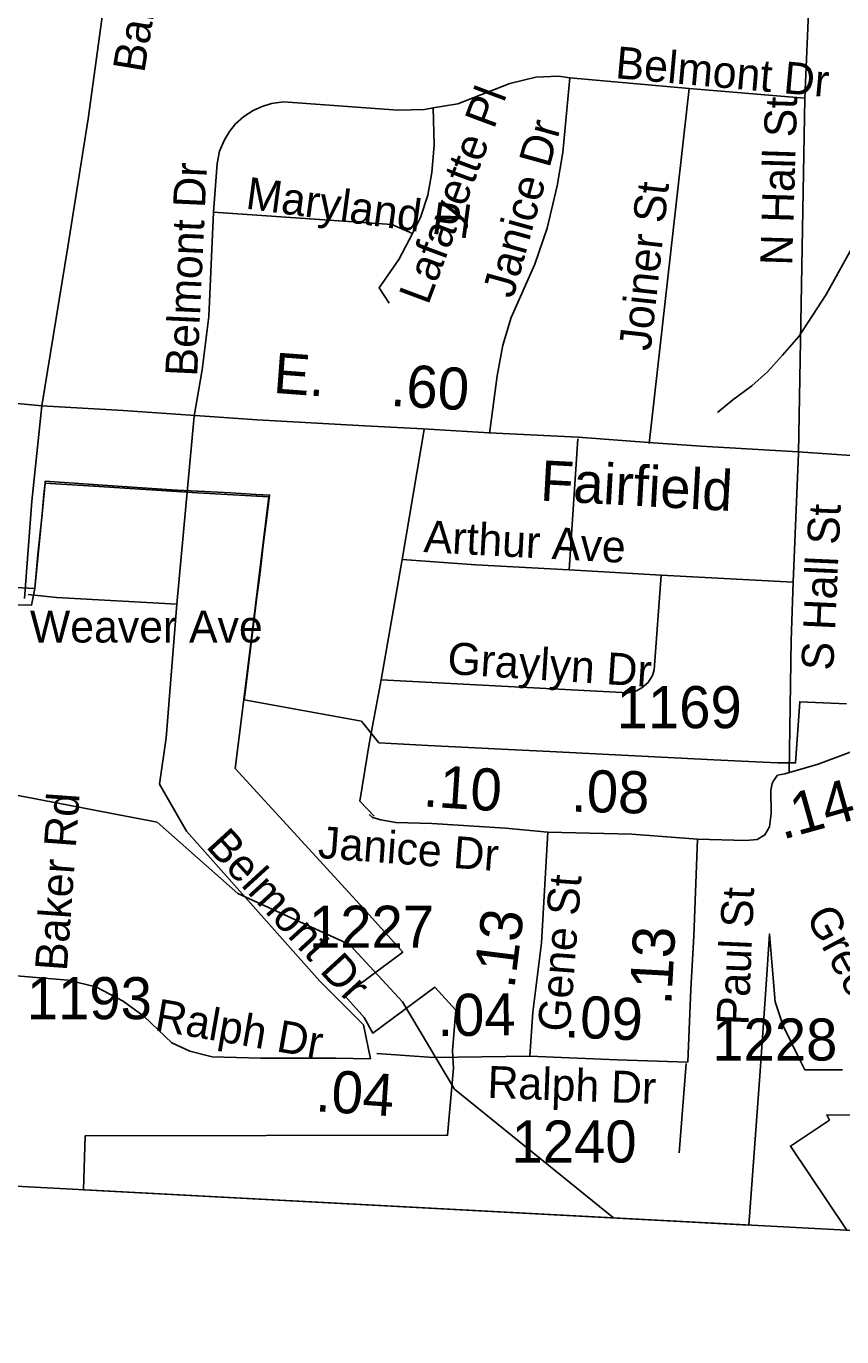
# Model space of a CAD drawing. Extents: x 1662474 to 1856135, y 779280 to 917889.
# Drawn here: x 1711933 to 1714357, y 789954 to 793848 of the extents above; entities that cross this region are included whole.
import ezdxf

# ---------------------------------------------------------------- set-up
doc = ezdxf.new("R2010")
doc.units = 0
for name, color, linetype in [('Exist Boundary Political City Limit New', 7, 'Continuous'), ('Exist Boundary Political CountyLine', 7, 'Continuous'), ('Exist Hydrographic Misc Water Feature', 7, 'Continuous'), ('Exist Road Non-System Type 51', 7, 'Continuous'), ('Exist Road Non-System Type 51 Label', 7, 'Continuous'), ('Exist Road Primary NC Attributed', 7, 'Continuous'), ('Exist Road Primary NC Label', 7, 'Continuous'), ('Exist Road Primary NC Mileage Hundredths English Label', 7, 'Continuous'), ('Exist Road Secondary Mileage Hundredths English Label', 7, 'Continuous'), ('Exist Road Secondary Mileage Tenths English Label', 7, 'Continuous'), ('Exist Road Secondary Type 51 Attributed', 7, 'Continuous'), ('Exist Road Secondary Type 51 Label', 7, 'Continuous'), ('Exist Road Secondary Type 51 Number Label', 7, 'Continuous'), ('Map Preparation Boundary City Limit Buffer Line', 7, 'Continuous')]:
    doc.layers.add(name, color=color, linetype=linetype)

msp = doc.modelspace()

# ---------------------------------------------------------------- linework, layer by layer
at = {"layer": 'Exist Boundary Political City Limit New'}
for points in [[(1711989.4, 792490.1), (1711958.4, 792176.9), (1711949.4, 792127.5), (1711899.6, 792128.6), (1711739.2, 792144.4), (1711711.2, 792147.1), (1711696, 792037.6), (1711687.4, 791927.7), (1711222.6, 791971.8), (1711122.2, 791981.2), (1711099.5, 791754.2), (1711348.9, 791737.2), (1711348.4, 791735.3), (1711873.5, 791696.8), (1711809, 790781.6), (1711807.5, 790781.6)], [(1711958.4, 792176.9), (1711968.9, 792288.8), (1711969.6, 792297.1), (1711980.4, 792396.9), (1711985.1, 792446.6), (1711988.8, 792483.4), (1711989.4, 792490.1)], [(1711989.4, 792490.1), (1711990, 792496.5), (1712189.4, 792482.6), (1712233.1, 792479.6), (1712293, 792475.4), (1712365.8, 792470.3), (1712382.8, 792469.1), (1712442.6, 792466.4), (1712444, 792466.3), (1712540.8, 792461.1), (1712616.2, 792456.9), (1712656.2, 792454.8), (1712650.1, 792405.1), (1712642.5, 792343.5), (1712637.8, 792305.5), (1712631.1, 792251.9), (1712630.1, 792244.1), (1712629, 792234.6), (1712625, 792202.1), (1712618.8, 792152.4), (1712611.6, 792094.7), (1712605.5, 792045.3), (1712598.8, 791990.9), (1712584.6, 791876.6), (1712580.9, 791846.5), (1712929.4, 791783.3), (1712981.2, 791718.6), (1713127.8, 791710.8), (1713247.6, 791704.7), (1713345.4, 791699.7), (1713488.8, 791692.4), (1713605.6, 791686.5), (1713722.8, 791680.6), (1713976.5, 791667.8), (1714122.5, 791660.9), (1714167.1, 791658.8), (1714219.4, 791658.8), (1714231.8, 791840.6), (1714370.4, 791834.7)], [(1714358.4, 790746.9), (1714246.8, 790747.2), (1714225.5, 790790.6), (1714182.6, 790877.9), (1714165.5, 790928.5), (1714159.1, 790948.9), (1714150, 791055.3), (1714141.8, 791150.6), (1714131.6, 791000.4), (1714113.4, 790729.3), (1714080, 790285.9), (1712103.2, 790390.4), (1712108.1, 790550.5), (1713185.5, 790552.5), (1713202.9, 790752.4), (1713200.4, 790803.4), (1713209.4, 790923.9), (1713147.2, 790992.4), (1712963, 790856.2), (1712937.8, 790902.4), (1712922.4, 790919.8), (1712878.6, 790968.1), (1713052.8, 791096.7), (1712925.4, 791237.1), (1712554.5, 791642.4), (1712591.6, 791942.1), (1712654.5, 792449.4), (1712442.1, 792461), (1712134.6, 792480.9), (1711989.4, 792490.1)], [(1711902.6, 792180.4), (1711958.4, 792176.9)], [(1714372.1, 790270.5), (1714204.1, 790520.2), (1714319.8, 790597.5), (1714312.2, 790612.9), (1714424, 790611.8)]]:
    msp.add_lwpolyline(points, dxfattribs=at)
at = {"layer": 'Exist Boundary Political CountyLine'}
msp.add_lwpolyline([(1690037.5, 791664.5), (1701364.2, 790957.5), (1714716, 790252.3), (1740499.2, 788706.5), (1750629.1, 788065.3), (1759370.2, 787540.1), (1762189.4, 787333), (1768414.3, 786933.6), (1776472.8, 786425.7), (1794607.1, 785397.2), (1814974.6, 784258.7), (1839558.3, 782880.6)], dxfattribs=at)
at = {"layer": 'Exist Hydrographic Misc Water Feature'}
for points in [[(1715151.2, 794379.7), (1715141, 794365.8), (1715053.8, 794246.6), (1714960.6, 794117.5), (1714899.6, 794006), (1714856.7, 793918.3), (1714791.8, 793826.9), (1714746.9, 793737.3), (1714661.5, 793598.1), (1714625, 793542.4), (1714590.6, 793492.7), (1714550.2, 793443.1), (1714507.5, 793385.5), (1714424.3, 793258.2), (1714375.4, 793168.7), (1714310.3, 793051.3), (1714229.2, 792925.9), (1714180.6, 792870.4), (1714136.1, 792820.9), (1714089.6, 792779.3), (1714033.2, 792737.8), (1713986.9, 792700.2)], [(1713678.2, 790307.1), (1713206.2, 790690), (1713051.1, 790949.2), (1712894.2, 791119.8), (1712562.1, 791271), (1712322.1, 791482.7), (1710999.1, 791736.1)]]:
    msp.add_lwpolyline(points, dxfattribs=at)
at = {"layer": 'Exist Road Non-System Type 51'}
for p, q in [((1714247.1, 793634.4), (1714260.6, 793950.8)), ((1713548.5, 793694.9), (1713903.4, 793663.1)), ((1713783.9, 792608), (1713903.4, 793663.1)), ((1713903.4, 793663.1), (1714247.1, 793634.4)), ((1714227.8, 792579.6), (1714247.1, 793634.4)), ((1712380.4, 792130.9), (1712432.5, 792689.6)), ((1713115.5, 792649.4), (1713050.4, 792263.6)), ((1713572.1, 792621.9), (1713546.6, 792232.4)), ((1714227.8, 792579.6), (1714212, 792195.9)), ((1713050.4, 792263.6), (1712987.9, 791905.6)), ((1713546.6, 792232.4), (1713820.4, 792217.2)), ((1713820.4, 792217.2), (1714212, 792195.9)), ((1713893.9, 790765.8), (1713873.1, 790500.2))]:
    msp.add_line(p, q, dxfattribs=at)
for points in [[(1713142.8, 793605.4), (1713215.8, 793617.7), (1713370.1, 793677.5), (1713447.2, 793696.4), (1713515.1, 793699.6), (1713548.5, 793694.9)], [(1713548.5, 793694.9), (1713527.5, 793473), (1713511, 793373.4), (1713481.1, 793247.6), (1713444.1, 793141.2), (1713374.5, 792982), (1713349.9, 792900.4), (1713332.8, 792809.2), (1713309.4, 792638.2)], [(1712490.2, 793295.6), (1712500.2, 793439.7), (1712508.1, 793476.4), (1712522, 793510.4), (1712537.2, 793535.5), (1712555.6, 793557.9), (1712580, 793579.9), (1712607.4, 793597.7), (1712633.9, 793609.8), (1712661.9, 793618.2), (1712698.1, 793622.9), (1713037.8, 793598.5), (1713116.5, 793600.4), (1713142.8, 793605.4)], [(1713142.8, 793605.4), (1713145.4, 793494.9), (1713138.9, 793412.9), (1713126.5, 793346.2), (1713104.6, 793279.4), (1713081.4, 793231.6)], [(1712490.2, 793295.6), (1712476.4, 792985.7), (1712456.1, 792826.6), (1712432.5, 792689.6)], [(1712490.2, 793295.6), (1713019.9, 793258.9), (1713081.4, 793231.6)], [(1713081.4, 793231.6), (1713040.1, 793155.2), (1712981.9, 793070.4), (1713011.5, 793025.5)], [(1713050.4, 792263.6), (1713268.8, 792247.9), (1713546.6, 792232.4)], [(1712987.9, 791905.6), (1713722.9, 791867), (1713746.6, 791873.4), (1713762.9, 791881.8), (1713781.1, 791897.8), (1713793.9, 791918.8), (1713799.4, 791935.9), (1713820.4, 792217.2)], [(1714212, 792195.9), (1714206.5, 792022.7), (1714199.9, 791631.4)], [(1711938.9, 792159.4), (1712022.9, 792150), (1712380.4, 792130.9)], [(1712955.9, 790779.2), (1712935.6, 790880.7), (1712805.5, 791010.9), (1712409.1, 791456.5), (1712329.6, 791595.4), (1712349.6, 791733.7), (1712380.4, 792130.9)], [(1712987.9, 791905.6), (1712952.2, 791715.6), (1712924.6, 791545.8), (1712966.7, 791500.6)], [(1711856.9, 791030.5), (1712057.9, 791013.4), (1712140.1, 790994.1), (1712221, 790951.4), (1712283.4, 790905.7), (1712366.1, 790827.2), (1712419.9, 790802.2), (1712485.9, 790785.9), (1712630.4, 790781.8), (1712853.5, 790781.8), (1712955.9, 790779.2)]]:
    msp.add_lwpolyline(points, dxfattribs=at)
at = {"layer": 'Exist Road Primary NC Attributed'}
for points in [[(1709810.5, 792964.2), (1710227.5, 793013.7), (1710304.9, 793022.3), (1710368.3, 793029.3), (1710434.8, 793035.6), (1710492.6, 793031.6), (1710554.4, 793024.6), (1710629.9, 793001.9), (1710677.6, 792982.4), (1710737.8, 792948), (1710833.3, 792892.9), (1710920.8, 792844.7), (1710990, 792811.9), (1711028.4, 792797.8), (1711083.9, 792783.7), (1711138.6, 792773.6), (1711202, 792766.5), (1711325.5, 792760.3), (1711389.7, 792756.4), (1711580.4, 792746.3), (1711834.2, 792733.6), (1711980.1, 792720.4)], [(1711980.1, 792720.4), (1712221, 792706.3), (1712434.9, 792691.5), (1712619.8, 792678.2), (1712939.3, 792660.2), (1713112.9, 792651.6), (1713308.8, 792639.8), (1713573.2, 792626.5), (1713782.4, 792610.9), (1713938.8, 792599.9), (1714227, 792583.5), (1714556.6, 792560.8), (1714732.6, 792548.3), (1714909.3, 792539.7), (1715082.8, 792532.6), (1715161.7, 792534.6)]]:
    msp.add_lwpolyline(points, dxfattribs=at)
at = {"layer": 'Exist Road Secondary Type 51 Attributed'}
for points in [[(1711980.1, 792720.4), (1712057.3, 793192.1), (1712117.7, 793573.1), (1712168.9, 793949.6), (1712234, 794372.5), (1712271.2, 794651.3), (1712289.2, 794759), (1712329.2, 794912.6), (1712473.9, 795357.1), (1712559.9, 795520.4), (1712593.7, 795605.5), (1712625.8, 795705.1), (1712648.3, 795803), (1712674.7, 795925.5), (1712699.3, 796156.8), (1712781.9, 796663.3), (1712836.2, 796867.3), (1712887.2, 796972.5), (1712944.6, 797071.4), (1713225.3, 797396.5), (1713368.9, 797536.8), (1713589, 797689.8), (1713974.4, 797851.7), (1714335.6, 798017.4)], [(1711927.7, 792148), (1711949.8, 792437), (1711980.1, 792720.4)], [(1714478.4, 791728.6), (1714436.3, 791713.1), (1714368.6, 791686), (1714286, 791654.9), (1714187, 791627), (1714166.1, 791622.4), (1714153.9, 791606.1), (1714149.8, 791598), (1714145.7, 791577.7), (1714147.1, 791508.7), (1714141.7, 791469.4), (1714128.1, 791445), (1714105.1, 791431.5), (1714071.2, 791428.8), (1713927.6, 791432.8)], [(1713482.8, 791453.6), (1713357.1, 791464.6), (1713138.3, 791478.8), (1713031.6, 791482.3), (1712987.2, 791489.5), (1712962.3, 791496.6), (1712952.8, 791505.3)], [(1713482.8, 791453.6), (1713464, 791124.1), (1713438.2, 790918.7), (1713429.4, 790787.8)], [(1713927.6, 791432.8), (1713733.1, 791446.9), (1713482.8, 791453.6)], [(1713927.6, 791432.8), (1713917.2, 791144.4), (1713908.6, 790986.3), (1713898.9, 790769.3)], [(1713429.4, 790787.8), (1713143.9, 790784.1), (1712975.4, 790795.5)], [(1713898.9, 790769.3), (1713688.8, 790776.3), (1713429.4, 790787.8)]]:
    msp.add_lwpolyline(points, dxfattribs=at)
at = {"layer": 'Map Preparation Boundary City Limit Buffer Line'}
for points in [[(1711989.4, 792490.1), (1711958.4, 792176.9), (1711949.4, 792127.5), (1711899.6, 792128.6), (1711739.2, 792144.4), (1711711.2, 792147.1), (1711696, 792037.6), (1711687.4, 791927.7), (1711222.6, 791971.8), (1711122.2, 791981.2), (1711099.5, 791754.2), (1711348.9, 791737.2), (1711348.4, 791735.3), (1711873.5, 791696.8), (1711809, 790781.6), (1711807.5, 790781.6)], [(1711958.4, 792176.9), (1711968.9, 792288.8), (1711969.6, 792297.1), (1711980.4, 792396.9), (1711985.1, 792446.6), (1711988.8, 792483.4), (1711989.4, 792490.1)], [(1711989.4, 792490.1), (1711990, 792496.5), (1712189.4, 792482.6), (1712233.1, 792479.6), (1712293, 792475.4), (1712365.8, 792470.3), (1712382.8, 792469.1), (1712442.6, 792466.4), (1712444, 792466.3), (1712540.8, 792461.1), (1712616.2, 792456.9), (1712656.2, 792454.8), (1712650.1, 792405.1), (1712642.5, 792343.5), (1712637.8, 792305.5), (1712631.1, 792251.9), (1712630.1, 792244.1), (1712629, 792234.6), (1712625, 792202.1), (1712618.8, 792152.4), (1712611.6, 792094.7), (1712605.5, 792045.3), (1712598.8, 791990.9), (1712584.6, 791876.6), (1712580.9, 791846.5), (1712929.4, 791783.3), (1712981.2, 791718.6), (1713127.8, 791710.8), (1713247.6, 791704.7), (1713345.4, 791699.7), (1713488.8, 791692.4), (1713605.6, 791686.5), (1713722.8, 791680.6), (1713976.5, 791667.8), (1714122.5, 791660.9), (1714167.1, 791658.8), (1714219.4, 791658.8), (1714231.8, 791840.6), (1714370.4, 791834.7)], [(1714358.4, 790746.9), (1714246.8, 790747.2), (1714225.5, 790790.6), (1714182.6, 790877.9), (1714165.5, 790928.5), (1714159.1, 790948.9), (1714150, 791055.3), (1714141.8, 791150.6), (1714131.6, 791000.4), (1714113.4, 790729.3), (1714080, 790285.9), (1712103.2, 790390.4), (1712108.1, 790550.5), (1713185.5, 790552.5), (1713202.9, 790752.4), (1713200.4, 790803.4), (1713209.4, 790923.9), (1713147.2, 790992.4), (1712963, 790856.2), (1712937.8, 790902.4), (1712922.4, 790919.8), (1712878.6, 790968.1), (1713052.8, 791096.7), (1712925.4, 791237.1), (1712554.5, 791642.4), (1712591.6, 791942.1), (1712654.5, 792449.4), (1712442.1, 792461), (1712134.6, 792480.9), (1711989.4, 792490.1)], [(1711902.6, 792180.4), (1711958.4, 792176.9)], [(1714372.1, 790270.5), (1714204.1, 790520.2), (1714319.8, 790597.5), (1714312.2, 790612.9), (1714424, 790611.8)]]:
    msp.add_lwpolyline(points, dxfattribs=at)

# ---------------------------------------------------------------- texts
at = {"layer": 'Exist Road Non-System Type 51 Label'}
for s, rotation, p in [('Belmont Dr', 354.8701, (1713681.7, 793693.9)), ('Lafayette Pl', 69.4915, (1713127.4, 793017)), ('N Hall St', 88.2649, (1714209, 793136)), ('Janice Dr', 74.4822, (1713379.9, 793036.4)), ('Belmont Dr', 87.3553, (1712441.2, 792805.9)), ('Maryland Pl', 352.3577, (1712582.7, 793306.3)), ('Joiner St', 83.7296, (1713788.5, 792881.3)), ('S Hall St', 87.3873, (1714331.1, 791932.2)), ('Arthur Ave', 356.8988, (1713112.8, 792285.6)), ('Graylyn Dr', 356.3146, (1713182.9, 791923.5)), ('Belmont Dr', 312.4177, (1712464.4, 791409.7)), ('Ralph Dr', 350.1354, (1712311.8, 790865.3))]:
    msp.add_text(s, height=95, rotation=rotation, dxfattribs=at).set_placement(p)
msp.add_text('Weaver Ave', height=95, dxfattribs=at).set_placement((1711944.2, 792016.7))
at = {"layer": 'Exist Road Primary NC Label'}
for s, rotation, p in [('E.', 355.7598, (1712665.5, 792758.8)), ('Fairfield', 356.8434, (1713458.9, 792438.7))]:
    msp.add_text(s, height=120, rotation=rotation, dxfattribs=at).set_placement(p)
at = {"layer": 'Exist Road Primary NC Mileage Hundredths English Label'}
msp.add_text('.60', height=125, rotation=356.5732, dxfattribs=at).set_placement((1713013.6, 792720.1))
at = {"layer": 'Exist Road Secondary Mileage Hundredths English Label'}
for s, rotation, p in [('.08', 358.4487, (1713551.2, 791514.3)), ('.14', 15.7181, (1714180.3, 791430.4)), ('.13', 82.8377, (1713383.5, 790985.3)), ('.04', 0.7479, (1713155.9, 790846.8)), ('.04', 356.1322, (1712790.8, 790624.2))]:
    msp.add_text(s, height=125, rotation=rotation, dxfattribs=at).set_placement(p)
at = {"layer": 'Exist Road Secondary Mileage Tenths English Label'}
for s, rotation, p in [('.10', 356.2816, (1713110.6, 791529.9)), ('.13', 86.8869, (1713849.9, 790937.6)), ('.09', 357.4458, (1713530.5, 790844.1))]:
    msp.add_text(s, height=125, rotation=rotation, dxfattribs=at).set_placement(p)
at = {"layer": 'Exist Road Secondary Type 51 Label'}
for s, rotation, p in [('Baker Rd', 80.6609, (1712283.9, 793707.3)), ('Baker Rd', 85.8448, (1712053.9, 791038.8)), ('Janice Dr', 355.7824, (1712798.5, 791376.8)), ('Gene St', 85.6491, (1713547.9, 790857.9)), ('Paul St', 87.6176, (1714079.2, 790878.3)), ('Greenoak Dr', 298.3055, (1714247.9, 791203.4)), ('Ralph Dr', 357.9, (1713302.6, 790664))]:
    msp.add_text(s, height=95, rotation=rotation, dxfattribs=at).set_placement(p)
at = {"layer": 'Exist Road Secondary Type 51 Number Label'}
for s, p in [('1169', (1713687.6, 791762.2)), ('1227', (1712773.5, 791109.7)), ('1193', (1711935, 790897.4)), ('1228', (1713971.7, 790774.6)), ('1240', (1713375.2, 790471.5))]:
    msp.add_text(s, height=125, dxfattribs=at).set_placement(p)

doc.saveas('drawing.dxf')
